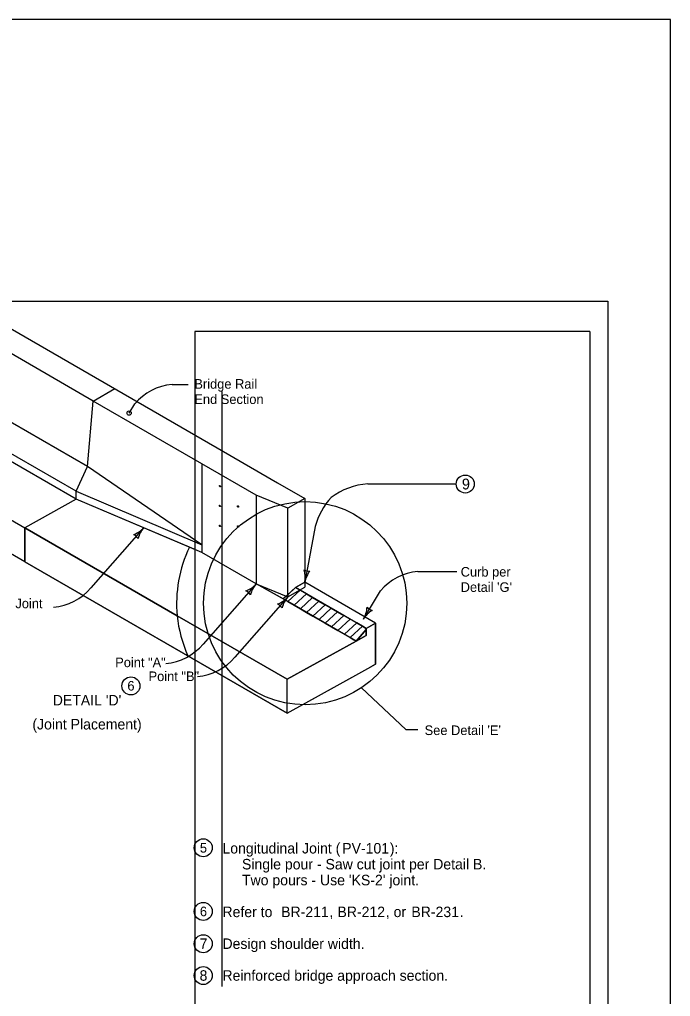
# Model space of a CAD drawing. Extents: x -2135039 to -2124495, y -2139046 to -2132546.
# Drawn here: x -2125580 to -2124495, y -2134174 to -2132546 of the extents above; entities that cross this region are included whole.
import ezdxf

# ---------------------------------------------------------------- set-up
doc = ezdxf.new("R2010")
doc.units = 0
for name, color, linetype in [('Barrier', 7, 'Continuous'), ('BridgeSuperStructureExisting', 7, 'Continuous'), ('Default', 7, 'Continuous'), ('dsnAlignmentStation', 7, 'Continuous'), ('dsnCellElements', 7, 'Continuous'), ('dsnStdLabel', 7, 'Continuous'), ('dsnStdLineWork', 7, 'Continuous'), ('PhoEdgeShoulderPaved', 7, 'Continuous'), ('TC_Barrier', 7, 'Continuous')]:
    doc.layers.add(name, color=color, linetype=linetype)

msp = doc.modelspace()

# ---------------------------------------------------------------- linework, layer by layer
at = {"layer": 'BridgeSuperStructureExisting'}
for p, q in [((-2125325.5, -2133154.6), (-2125298.6, -2133154.6)), ((-2125466.3, -2133291.3), (-2125651.3, -2133184.5)), ((-2125397, -2133202.2), (-2125387.7, -2133187)), ((-2125485.2, -2133332.6), (-2125670.2, -2133225.8)), ((-2125275.9, -2133286.7), (-2125275.9, -2133434.5)), ((-2124999.3, -2133320), (-2124851.8, -2133320)), ((-2125485.2, -2133345.7), (-2125571, -2133393.3)), ((-2125485.2, -2133345.7), (-2125571, -2133393.3)), ((-2125296.5, -2133425.8), (-2125485.2, -2133345.7)), ((-2125275.9, -2133434.5), (-2125485.2, -2133345.7)), ((-2125185.3, -2133338.9), (-2125185.3, -2133486.8)), ((-2125104.3, -2133344.4), (-2125104.3, -2133484.2)), ((-2125132.5, -2133505), (-2125132.5, -2133360.7)), ((-2125571, -2133393.3), (-2125571, -2133449.9)), ((-2125316.9, -2133540), (-2125571, -2133393.3)), ((-2125571, -2133393.3), (-2125571, -2133449.9)), ((-2125571, -2133393.3), (-2125316.9, -2133540)), ((-2125571, -2133393.3), (-2125133.8, -2133645.8)), ((-2125372.5, -2133393), (-2125460.9, -2133493.4)), ((-2125087, -2133391.2), (-2125104.3, -2133484.2)), ((-2125275.9, -2133434.5), (-2125296.5, -2133425.8)), ((-2125571, -2133449.9), (-2125133.8, -2133702.4)), ((-2125571, -2133449.9), (-2125299.1, -2133606.9)), ((-2125133.8, -2133702.4), (-2125571, -2133449.9)), ((-2125185.3, -2133486.8), (-2125275.9, -2133434.5)), ((-2125185.3, -2133486.8), (-2125275.9, -2133434.5)), ((-2124915.9, -2133466.1), (-2124850.7, -2133466.1)), ((-2125185.3, -2133486.8), (-2125273.8, -2133587.1)), ((-2125132.5, -2133516.4), (-2125185.3, -2133486.8)), ((-2125140.1, -2133512), (-2125185.3, -2133486.8)), ((-2125119.7, -2133493.1), (-2125132.5, -2133505)), ((-2125112.1, -2133497.4), (-2125132.5, -2133516.4)), ((-2125112.1, -2133497.4), (-2125132.5, -2133516.4)), ((-2125104.3, -2133484.2), (-2125119.7, -2133493.1)), ((-2125119.7, -2133493.1), (-2125101.7, -2133503.4)), ((-2125001.9, -2133561), (-2125119.7, -2133493.1)), ((-2125101.7, -2133503.4), (-2125112.1, -2133497.4)), ((-2124986.2, -2133552.3), (-2125104.3, -2133484.2)), ((-2124986.2, -2133552.3), (-2125104.3, -2133484.2)), ((-2125104.3, -2133484.2), (-2125104.3, -2133492.2)), ((-2125006.7, -2133545.6), (-2124978.1, -2133498.5)), ((-2125132.5, -2133508.6), (-2125221, -2133608.9)), ((-2125132.5, -2133505), (-2125140.1, -2133512)), ((-2125018.8, -2133582), (-2125140.1, -2133512)), ((-2125132.5, -2133505), (-2125132.5, -2133508.6)), ((-2125122.1, -2133522.4), (-2125101.7, -2133503.4)), ((-2125101.7, -2133503.4), (-2125122.1, -2133522.4)), ((-2125101.7, -2133503.4), (-2125122.1, -2133522.4)), ((-2125111.7, -2133528.4), (-2125091.3, -2133509.4)), ((-2125091.3, -2133509.4), (-2125111.7, -2133528.4)), ((-2125091.3, -2133509.4), (-2125111.7, -2133528.4)), ((-2125091.3, -2133509.4), (-2125101.7, -2133503.4)), ((-2125101.7, -2133503.4), (-2125091.3, -2133509.4)), ((-2125080.9, -2133515.4), (-2125091.3, -2133509.4)), ((-2125091.3, -2133509.4), (-2125080.9, -2133515.4)), ((-2125122.1, -2133522.4), (-2125132.5, -2133516.4)), ((-2125132.5, -2133516.4), (-2125122.1, -2133522.4)), ((-2125022.4, -2133580), (-2125132.5, -2133516.4)), ((-2125122.1, -2133522.4), (-2125111.7, -2133528.4)), ((-2125111.7, -2133528.4), (-2125101.3, -2133534.4)), ((-2125101.3, -2133534.4), (-2125080.9, -2133515.4)), ((-2125080.9, -2133515.4), (-2125101.3, -2133534.4)), ((-2125080.9, -2133515.4), (-2125101.3, -2133534.4)), ((-2125090.9, -2133540.4), (-2125070.5, -2133521.5)), ((-2125070.5, -2133521.5), (-2125090.9, -2133540.4)), ((-2125070.5, -2133521.5), (-2125090.9, -2133540.4)), ((-2125070.5, -2133521.5), (-2125080.9, -2133515.4)), ((-2125080.9, -2133515.4), (-2125070.5, -2133521.5)), ((-2125060.2, -2133527.4), (-2125080.3, -2133546)), ((-2125316.9, -2133540), (-2125133.8, -2133645.8)), ((-2125133.8, -2133645.8), (-2125316.9, -2133540)), ((-2125101.3, -2133534.4), (-2125090.9, -2133540.4)), ((-2125090.9, -2133540.4), (-2125070.1, -2133552.4)), ((-2125070.1, -2133552.4), (-2125049.7, -2133533.5)), ((-2125049.7, -2133533.5), (-2125070.1, -2133552.4)), ((-2125049.7, -2133533.5), (-2125070.1, -2133552.4)), ((-2125059.7, -2133558.4), (-2125039.3, -2133539.5)), ((-2125039.3, -2133539.5), (-2125059.7, -2133558.4)), ((-2125039.3, -2133539.5), (-2125059.7, -2133558.4)), ((-2125039.3, -2133539.5), (-2125049.7, -2133533.5)), ((-2125049.7, -2133533.5), (-2125039.3, -2133539.5)), ((-2125028.8, -2133545.5), (-2125049.2, -2133564.5)), ((-2125070.1, -2133552.4), (-2125059.7, -2133558.4)), ((-2125059.7, -2133558.4), (-2125049.2, -2133564.5)), ((-2125017.8, -2133551.9), (-2125038.2, -2133570.8)), ((-2125028.5, -2133576.4), (-2125008.1, -2133557.5)), ((-2125008.1, -2133557.5), (-2125028.5, -2133576.4)), ((-2125008.1, -2133557.5), (-2125028.5, -2133576.4)), ((-2125018.8, -2133582), (-2125001.9, -2133562.9)), ((-2125001.9, -2133562.9), (-2125018.8, -2133582)), ((-2125018.8, -2133582), (-2125001.9, -2133562.9)), ((-2125001.9, -2133561), (-2125008.1, -2133557.5)), ((-2125008.1, -2133557.5), (-2125001.9, -2133561)), ((-2124994.1, -2133556.7), (-2125001.9, -2133561)), ((-2125001.9, -2133561), (-2124994.1, -2133556.7)), ((-2124994.1, -2133556.7), (-2125001.9, -2133561)), ((-2125001.9, -2133562.9), (-2125001.9, -2133561)), ((-2125001.9, -2133572.7), (-2125001.9, -2133562.9)), ((-2124986.2, -2133552.3), (-2124994.1, -2133556.7)), ((-2124994.1, -2133556.7), (-2124986.2, -2133552.3)), ((-2124986.2, -2133552.3), (-2124994.1, -2133556.7)), ((-2124986.2, -2133620.6), (-2124986.2, -2133552.3)), ((-2125049.2, -2133564.5), (-2125028.5, -2133576.4)), ((-2125028.5, -2133576.4), (-2125022.4, -2133580)), ((-2125018.8, -2133582), (-2125022.4, -2133580)), ((-2125022.4, -2133580), (-2125018.8, -2133582)), ((-2125001.9, -2133572.7), (-2125018.8, -2133582)), ((-2125018.8, -2133582), (-2125001.9, -2133572.7)), ((-2125133.8, -2133645.8), (-2125018.8, -2133582)), ((-2125018.8, -2133582), (-2125133.8, -2133645.8)), ((-2125133.8, -2133645.8), (-2125018.8, -2133582)), ((-2125299.1, -2133606.9), (-2125133.8, -2133702.4)), ((-2125029.3, -2133644.5), (-2124994.1, -2133624.9)), ((-2125009.2, -2133633.3), (-2124994.1, -2133624.9)), ((-2124994.1, -2133624.9), (-2124986.2, -2133620.6)), ((-2124986.2, -2133620.6), (-2124994.1, -2133624.9)), ((-2125133.8, -2133702.4), (-2125009.2, -2133633.3)), ((-2125133.8, -2133702.4), (-2125133.8, -2133645.8)), ((-2125009.6, -2133659.9), (-2124935.9, -2133729.3)), ((-2124935.9, -2133729.3), (-2124916.1, -2133729.3))]:
    msp.add_line(p, q, dxfattribs=at)
for points in [[(-2125606, -2133054.7), (-2125240, -2133266), (-2125149.5, -2133318.2), (-2125104.3, -2133344.4), (-2125132.5, -2133360.7), (-2125185.3, -2133338.9), (-2125275.9, -2133286.7), (-2125456.9, -2133182.1), (-2125641.9, -2133075.3)], [(-2125456.9, -2133182.1), (-2125421, -2133161.5)], [(-2125485.2, -2133345.7), (-2125485.2, -2133332.6), (-2125466.3, -2133291.3), (-2125456.9, -2133182.1)], [(-2125485.2, -2133345.7), (-2125670.2, -2133238.9)], [(-2125756, -2133286.5), (-2125571, -2133393.3)], [(-2125485.2, -2133332.6), (-2125275.9, -2133421.5), (-2125466.3, -2133291.3)], [(-2125571, -2133449.9), (-2125756, -2133343.1)], [(-2125485.2, -2133345.7), (-2125571, -2133393.3)], [(-2125571, -2133449.9), (-2125571, -2133393.3)], [(-2125104.3, -2133484.2), (-2125104.3, -2133484.2), (-2125104.3, -2133484.2)], [(-2125101.3, -2133534.4), (-2125111.7, -2133528.4), (-2125122.1, -2133522.4)], [(-2125049.7, -2133533.5), (-2125060.2, -2133527.4), (-2125070.5, -2133521.5)], [(-2125070.5, -2133521.5), (-2125060.2, -2133527.4), (-2125049.7, -2133533.5)], [(-2125070.1, -2133552.4), (-2125090.9, -2133540.4), (-2125101.3, -2133534.4)], [(-2125008.1, -2133557.5), (-2125017.8, -2133551.9), (-2125039.3, -2133539.5)], [(-2125039.3, -2133539.5), (-2125017.8, -2133551.9), (-2125008.1, -2133557.5)], [(-2125022.4, -2133580), (-2125028.5, -2133576.4), (-2125049.2, -2133564.5), (-2125059.7, -2133558.4), (-2125070.1, -2133552.4)], [(-2125001.9, -2133561), (-2125001.9, -2133562.9), (-2125001.9, -2133572.7)], [(-2124986.2, -2133552.3), (-2124986.2, -2133620.6)], [(-2125133.8, -2133702.4), (-2125029.3, -2133644.5), (-2125009.2, -2133633.3)]]:
    msp.add_lwpolyline(points, dxfattribs=at)
for points in [[(-2125140.1, -2133512), (-2125132.5, -2133516.4), (-2125185.3, -2133486.8), (-2125135.2, -2133507.5)], [(-2125140.1, -2133512), (-2125119.7, -2133493.1), (-2125112.1, -2133497.4), (-2125132.5, -2133516.4)]]:
    msp.add_lwpolyline(points, close=True, dxfattribs=at)
for centre, radius in [((-2124836.9, -2133320.4), 15), ((-2125103.7, -2133519.1), 169.3), ((-2125394, -2133656.8), 15), ((-2125273.5, -2133926.6), 15), ((-2125273.5, -2134032.6), 15), ((-2125273.5, -2134086.4), 15), ((-2125273.5, -2134139.4), 15)]:
    msp.add_circle(centre, radius, dxfattribs=at)
for centre, radius, start, end in [((-2125317.8, -2133245.3), 91, 94.8409, 140.1467), ((-2124990.4, -2133437.2), 117.5, 94.3399, 126.627), ((-2124973.7, -2133422.1), 117.5, 137.5971, 164.7195), ((-2125103.7, -2133519.1), 214.2, 154.1687, 185.6063), ((-2125103.7, -2133519.1), 214.2, 154.1687, 185.6063), ((-2124908.2, -2133556.9), 91, 94.8409, 140.1467), ((-2125530.8, -2133435), 91, 274.8409, 320.1467), ((-2125103.7, -2133519.1), 214.2, 185.6063, 204.2018), ((-2125103.7, -2133519.1), 214.2, 185.6063, 204.2018), ((-2125343.7, -2133528.8), 91, 274.8409, 320.1467), ((-2125290.9, -2133550.6), 91, 274.8409, 320.1467)]:
    msp.add_arc(centre, radius, start, end, dxfattribs=at)
for centre in [(-2125245.7, -2133323.8), (-2125245.7, -2133357), (-2125215.5, -2133357.8), (-2125245.7, -2133390.2), (-2125215.5, -2133391)]:
    msp.add_ellipse(centre, major_axis=(0.67, -1.15), ratio=0.57735, dxfattribs=at)
at = {"layer": 'Default'}
for p, q in [((-2125185.3, -2133486.8), (-2125135.2, -2133507.5)), ((-2125132.5, -2133508.6), (-2125104.3, -2133492.2)), ((-2125119.7, -2133493.1), (-2125104.3, -2133484.2)), ((-2125135.2, -2133507.5), (-2125132.5, -2133508.6))]:
    msp.add_line(p, q, dxfattribs=at)
at = {"layer": 'dsnAlignmentStation'}
msp.add_lwpolyline([(-2127734.4, -2133016), (-2124599.4, -2133016), (-2124599.4, -2135026), (-2127734.4, -2135026)], close=True, dxfattribs=at)
at = {"layer": 'dsnCellElements'}
for centre, radius, start, end in [((-2125404.4, -2133364.9), 42.5, 290.5435, 318.616), ((-2125340.6, -2133421.1), 42.5, 138.616, 166.6885), ((-2125396, -2133419.8), 16.4, 30.8827, 66.3494), ((-2125097.8, -2133449.1), 16.4, 241.782, 277.2487), ((-2125146.1, -2133476.4), 42.5, 349.5153, 17.5878), ((-2125062.5, -2133491.9), 42.5, 141.4428, 169.5153), ((-2125217.2, -2133458.7), 42.5, 290.5435, 318.616), ((-2125208.9, -2133513.5), 16.4, 30.8827, 66.3494), ((-2125153.5, -2133514.9), 42.5, 138.616, 166.6885), ((-2125164.4, -2133480.5), 42.5, 290.5435, 318.616), ((-2125100.7, -2133536.7), 42.5, 138.616, 166.6885), ((-2125156.1, -2133535.3), 16.4, 30.8827, 66.3494), ((-2125043, -2133523.5), 42.5, 328.7108, 356.7833), ((-2124970.4, -2133567.6), 42.5, 120.6383, 148.7108), ((-2124988.2, -2133515.1), 16.4, 220.9775, 256.4442)]:
    msp.add_arc(centre, radius, start, end, dxfattribs=at)
at = {"layer": 'dsnStdLineWork'}
msp.add_lwpolyline([(-2127838.9, -2135130.5), (-2124494.9, -2135130.5), (-2124494.9, -2132546.5), (-2127838.9, -2132546.5)], close=True, dxfattribs=at)
at = {"layer": 'PhoEdgeShoulderPaved'}
for p, q in [((-2125287.5, -2133066), (-2125287.5, -2134535.9)), ((-2124629.4, -2133066), (-2125287.5, -2133066)), ((-2124629.4, -2133066), (-2124629.4, -2134535.9)), ((-2125242.5, -2133166), (-2125242.5, -2134157.5))]:
    msp.add_line(p, q, dxfattribs=at)
at = {"layer": 'TC_Barrier'}
msp.add_circle((-2125397, -2133202.2), 3.54, dxfattribs=at)

# ---------------------------------------------------------------- texts
at = {"layer": 'Barrier'}
for s, height, p in [('9', 18, (-2124842.5, -2133329.4)), ('5', 16, (-2125279.1, -2133934.6)), ('Longitudinal Joint (', 17.5, (-2125241.5, -2133936.1)), ('PV-101', 17.5, (-2125041.9, -2133936.1)), ('PV-101', 17.5, (-2125041.9, -2133936.1)), ('):', 17.5, (-2124962.6, -2133936.1)), ('     Single pour - Saw cut joint per Detail B.', 17.5, (-2125241.5, -2133962.6)), ("     Two pours - Use 'KS-2' joint.", 17.5, (-2125241.5, -2133989.1)), ('6', 16, (-2125279.1, -2134040.6)), ('Refer to ', 17.5, (-2125241.5, -2134042.1)), ('BR-211', 17.5, (-2125143.7, -2134042.1)), ('BR-211', 17.5, (-2125143.7, -2134042.1)), ('BR-212', 17.5, (-2125049.9, -2134042.1)), ('BR-212', 17.5, (-2125049.9, -2134042.1)), (', or ', 17.5, (-2124969.3, -2134042.1)), ('BR-231', 17.5, (-2124926.7, -2134042.1)), ('BR-231', 17.5, (-2124926.7, -2134042.1)), (', ', 17.5, (-2125063.1, -2134042.1)), ('.', 17.5, (-2124846.1, -2134042.1)), ('7', 17.5, (-2125279.5, -2134095.1)), ('Design shoulder width.', 17.5, (-2125241.5, -2134095.1)), ('8', 17.5, (-2125279.6, -2134148.1)), ('Reinforced bridge approach section.', 17.5, (-2125241.5, -2134148.1))]:
    msp.add_text(s, height=height, dxfattribs=at).set_placement(p)
at = {"layer": 'BridgeSuperStructureExisting'}
for s, height, p in [('Bridge Rail ', 16, (-2125288.3, -2133161.6)), ('End Section', 16, (-2125288.3, -2133187.1)), ('Curb per', 16, (-2124844.5, -2133474.7)), ("Detail 'G'", 16, (-2124844.5, -2133500.2)), ("'E' Joint", 16, (-2125614.9, -2133527.4)), ('Point "A"', 16, (-2125420.2, -2133625.6)), ('Point "B"', 16, (-2125364.6, -2133648.8)), ("DETAIL 'D'", 17.5, (-2125524.3, -2133689.4)), ("See Detail 'E'", 16, (-2124904.6, -2133738.7))]:
    msp.add_text(s, height=height, dxfattribs=at).set_placement(p)
at = {"layer": 'dsnStdLabel'}
for s, height, p in [('6', 16, (-2125399.9, -2133664.6)), ('(Joint Placement)', 17.5, (-2125558.2, -2133729.4))]:
    msp.add_text(s, height=height, dxfattribs=at).set_placement(p)

doc.saveas('drawing.dxf')
